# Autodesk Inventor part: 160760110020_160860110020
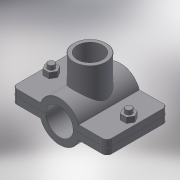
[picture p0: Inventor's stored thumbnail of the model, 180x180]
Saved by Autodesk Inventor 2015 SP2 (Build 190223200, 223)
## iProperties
Created: 2017-05
Part Number: 160760110020_160860110020
Material: Generic
Description: PLASSON SADDLE 110-2"
Document SubType Name: Modeling
Designer: KIM
Density: 1 g/cm^3
Appearance: Default
Author: KIM
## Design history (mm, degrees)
derived "16076.ipt"
feature "Solid1::16076.ipt"
feature "Solid2::16076.ipt"
tag "TaggingFeature1"
body "Solid1"
other parameters: "d0" = 121, "d1" = 165, "d2" = 55, "d4" = 116, "d5" = 0, "d6" = 8.25, "d7" = 165, "d8" = 0.1, "d10" = 0, "d11" = 1.1, "d14" = 73.6528, "d20" = 1.1, "d23" = 1.1, "d36" = 13, "d37" = 10.4, "d38" = 63, "d39" = 0, "d40" = 3, "d41" = 5, "d42" = 0, "d43" = 8, "d44" = 3, "d45" = 0, "d46" = 1.1, "d51" = 97, "d52" = 56.656, "d54" = 0, "d57" = 0, "d58" = 118.8, "d60" = 0, "d62" = 13, "d63" = 10.4, "d66" = 95.2, "G_" = 56.656, "A_" = 97, "L_" = 165, "L_1" = 116
